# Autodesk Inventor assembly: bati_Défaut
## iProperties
Shininess: 64.0
Length Units: 11269
Angle Units: 11279
Time Units: 11290
Mass Units: 11283
Length Display Precision: 3
Angle Display Precision: 2
Compacted: True
Created: 2006-11
Part Number: bati_Défaut
Document SubType Name: Assembly
Designer: profs_sti
Density: 0.0
Volumn: 0.0
Area: 0.0
PropertySet Name: Model Information
Control State: 0
Master: False
Checked Out: False
Author: profs_sti
